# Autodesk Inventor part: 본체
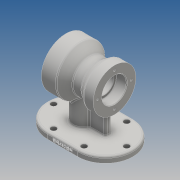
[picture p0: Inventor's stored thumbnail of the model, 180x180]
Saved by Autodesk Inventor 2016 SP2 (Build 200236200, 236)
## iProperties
Created: 2020-01
Part Number: 본체
Material: Generic
Document SubType Name: Modeling
Designer: EZ
Density: 1 g/cm^3
Appearance: Default
Mass: 347.448 g
Surface Area: 654.887 cm^2
Volume: 347.448 cm^3
Author: EZ
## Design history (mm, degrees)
sketch "스케치1"
  geometry: L1 (-70, -45)-(70, -45); L2 (70, -45)-(70, 45); L3 (70, 45)-(-70, 45); L4 (-70, 45)-(-70, -45); L5 (-70, -45)-(70, 45); L6 (70, -45)-(-70, 45); 1 further point
  constraints: 12 end point, 2 midpoint, 2 parallel, 1 horizontal, 1 perpendicular
  dimensions: "d0" = 140 distance of L3.end L2.end; "d1" = 90 distance of L2.end L1.end
extrude "돌출1" new body sketch "스케치1" distance "d2" = 10; taper "d3" = 0 deg
fillet "모깎기1" dims "d4" = 45
sketch "스케치2"
  geometry: L1 (40, 80)-(-40, 80); L2 (-25, 0)-(-70, 0) reference; L3 (70, 0)-(70, 10) reference; L4 (40, 80)-(40, 120); L5 (40, 120)-(16, 120); L6 (16, 120)-(1.103, 107.5); L7 (-24, 115)-(-40, 115); L8 (-40, 115)-(-40, 80); L9 (1.103, 107.5)-(-13.289, 107.5); L10 (-13.289, 107.5)-(-24, 115); 1 further point
  constraints: 16 end point, 2 horizontal, 2 perpendicular, 1 parallel, 1 vertical
  dimensions: "d5" = 80 distance of L1.start L1.end; "d6" = 80 distance between parallel lines of L2 L1; "d7" = 30 distance from line of L3 L1.start; "d8" = 24 distance from line of L5.end L4; "d10" = 70 diameter of L7 L1; "d12" = 80 diameter of L5 L1; "d14" = 35 deg angle of L9 L10; "d15" = 40 deg angle of L9 L6; "d16" = 55 diameter of L9 L1; "d17" = 16 distance from line of L7.start L8
revolve "회전1" sketch "스케치2" stored, may be unused: angle "d18" = 90 deg
sketch "스케치3"
  geometry: L1 (40, 40)-(40, 120) reference; L2 (-40, 45)-(-40, 115) reference; L3 (40, 80)-(-40, 80); L4 (40, 106)-(20, 106); L5 (20, 106)-(20, 96); L6 (20, 96)-(-23, 96); L7 (-23, 96)-(-23, 100); L8 (-23, 100)-(-40, 100); 1 further point
  constraints: 12 end point, 5 perpendicular, 2 midpoint, 2 point on line
  dimensions: "d19" = 52 diameter of L4 L3; "d20" = 32 diameter of L6 L3; "d21" = 40 diameter of L8 L3; "d22" = 20 distance between parallel lines of L5 L1; "d23" = 17 distance between parallel lines of L2 L7
revolve "회전2" sketch "스케치3" stored, may be unused: angle "d24" = 90 deg
sketch "스케치4"
  geometry: L1 (25, 45)-(-25, 45) reference; L2 (-25, -45)-(25, -45) reference; L3 (-70, 0)-(-72.967, 0); L4 (3.199, 5)-(30, 5); L5 (30, 5)-(30, -5); L6 (30, -5)-(3.199, -5); L7 (40, 35)-(40, -35) reference; A1 r 16 centre (-12, 0) between (3.199, 5) and (3.199, -5); A2 r 45 centre (-25, 0) between (-25, 45) and (-25, -45) reference; A3 r 45 centre (25, 0) between (25, -45) and (25, 45) reference; 1 further point
  constraints: 8 end point, 3 point on circle, 2 horizontal, 2 perpendicular, 1 centre point, 1 horizontal alignment, 1 parallel
  dimensions: "d25" = 32 diameter of A1; "d26" = 58 distance of A1.centre L3.start; "d27" = 10 distance between parallel lines of L6 L4; "d79" = 10 distance between parallel lines of L5 L7
extrude "돌출2" join sketch "스케치4" stored distance "d29" = 10; taper "d30" = 0 deg
sketch "스케치5"
  geometry: C1 r 26 at (0, 0) reference; C2 r 40 at (0, 0) reference; 2 further points
  constraints: 1 horizontal alignment
  dimensions: "d31" = 33 distance of C1.centre point (33, 0)
hole "구멍1" sketch "스케치5" at (33, 0) diameter "d32" = 3.242; stored, may be unused: countersink angle "d36" = 90 deg, drill point angle "d38" = 118 deg; dims "d33" = 9, "d34" = 4, "d35" = 2, "d37" = 11
sketch "스케치6"
  geometry: C1 r 20 at (0, 0) reference; C2 r 35 at (0, 0) reference; 2 further points
  constraints: 1 horizontal alignment
  dimensions: "d42" = 27.5 distance of C1.centre point (-27.5, 0)
hole "구멍2" sketch "스케치6" at (-27.5, 0) diameter "d43" = 3.242; stored, may be unused: countersink angle "d47" = 90 deg, drill point angle "d49" = 118 deg; dims "d44" = 9, "d45" = 4, "d46" = 2, "d48" = 11
sketch "스케치7"
  geometry: L1 (25, 45)-(-25, 45) reference; L2 (-25, -45)-(25, -45) reference; L3 (-25, 35)-(25, 35); L4 (25, -35)-(-25, -35); C1 r 4.5 at (-60, 0); C2 r 4.5 at (-25, 35); C3 r 4.5 at (-25, -35); C4 r 4.5 at (25, 35); C5 r 4.5 at (25, -35); C6 r 4.5 at (60, 0); A1 r 45 centre (-25, 0) between (-25, 45) and (-25, -45) reference; A2 r 45 centre (25, 0) between (25, -45) and (25, 45) reference; A3 r 35 centre (-25, 0) between (-25, 35) and (-25, -35); A4 r 35 centre (25, 0) between (25, -35) and (25, 35); 1 further point
  constraints: 8 centre point, 6 point on circle, 4 coincident, 4 end point, 3 other
  dimensions: "d54" = 10 radial gap between concentric circles of A1 A3; "d55" = 9 diameter of C1; "d56" = 9 diameter of C2; "d57" = 9 diameter of C3; "d58" = 9 diameter of C4; "d59" = 9 diameter of C5; "d60" = 9 diameter of C6
extrude "돌출3" cut sketch "스케치7" distance "d61" = 10; taper "d62" = 0 deg
fillet "모깎기5" dims "d66" = 3
fillet "모깎기6" dims "d67" = 3
fillet "모깎기7" dims "d68" = 3
fillet "모깎기8" dims "d69" = 3
sketch "스케치8"
  geometry: L1 (-45, 0)-(-45, 7) reference; 2 further points
  constraints: 1 other
  dimensions: "d70" = 4 distance of point (25, 0) point (25, 4); "d71" = 70 distance from line of point (25, 4) L1
feature "엠보싱1" sketch "스케치8" dims "d0" = 140, "d1" = 90, "d5" = 80, "d6" = 80, "d7" = 30, "d8" = 24, "d10" = 70, "d12" = 80, "d14" = 35 deg, "d15" = 40 deg, "d16" = 55, "d17" = 16, "d72" = 0.5, "d73" = 0
fillet "모깎기9" dims "d74" = 3
fillet "모깎기10" dims "d75" = 0.3
chamfer "모따기1" distance "d76" = 1; stored, may be unused: second distance "d77" = 2, angle "d78" = 45 deg
node "솔리드1"
pattern_circular "원형 패턴1" dims angle "d40" = 360 deg
pattern_circular "원형 패턴2" dims angle "d51" = 360 deg
node "투영된 루프1"
node "투영된 루프2"
node "투영된 루프3"
node "투영된 루프4"
